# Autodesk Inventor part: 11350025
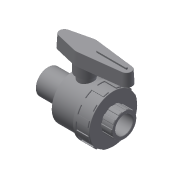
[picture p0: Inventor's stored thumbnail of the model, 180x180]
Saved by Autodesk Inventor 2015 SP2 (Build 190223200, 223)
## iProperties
Created: 2017-11
Part Number: 11350025
Material: Generic
Description: PLASSON 1/NUT VALVE CEM. PVC 25
Document SubType Name: Modeling
Designer: KIM
Density: 1 g/cm^3
Appearance: Default
Author: KIM
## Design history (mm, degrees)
derived "113500.ipt"
feature "Solid1::113500.ipt"
tag "TaggingFeature1"
body "Solid1"
other parameters: "d0" = 87, "d2" = 55, "d8" = 49.5, "d13" = 0.75, "d25" = 0.5, "d26" = 0.75, "d29" = 14.25, "d30" = 0, "d35" = 0.75, "d39" = 27.5, "d45" = 360 deg, "d47" = 0.5, "d50" = 30.25, "d51" = 16.5, "d53" = 0, "d55" = 5, "d56" = 2.5, "d57" = 13.3, "d58" = 0, "d59" = 0.75, "d63" = 22, "d64" = 54, "d66" = 73, "d68" = 11, "d69" = 21.9, "d70" = 13.5, "d71" = 3 deg, "d73" = 1.1, "d74" = 29.2, "d75" = 1.62, "d76" = 0, "d77" = 0.5, "d78" = 25, "d79" = 19, "d80" = 55, "d81" = 19, "d82" = 52.8, "d83" = 13.3, "d84" = 35, "d85" = 25, "d86" = 35, "d87" = 120 deg, "d88" = 19, "d90" = 360 deg, "d92" = 8.25, "d95" = 4.125, "d_" = 25, "l_" = 19, "H_" = 87, "K_" = 55, "F_" = 54, "J_" = 73, "d67" = 22, "d72" = 5.5
